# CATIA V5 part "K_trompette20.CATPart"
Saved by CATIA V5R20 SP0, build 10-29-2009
Part number: trompette20
Publications: "Droite.1", "Point.1", "Plan.3"
Bounding box of the stored display mesh (mm): x -49.997 to 49.997, y -49.994 to 49.994, z 0 to 320
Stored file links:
  G:\Khaled_CFAO_2011\SIL\SIL_GR1\gperrin\Khaled\CAD_CATIA\Khaled\K_trompette20.CATPart
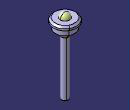
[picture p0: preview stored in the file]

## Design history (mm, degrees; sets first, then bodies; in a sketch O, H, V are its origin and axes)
Set1
  Plane1: stored without definition
  Plane2: stored without definition
  Point1: (0, 300, 0)
  Point2: (0, 0, 300)
  Point3: (0, 20, 300)
  Point4: type Center, Curve edge [face of Shaft1 from Sketch1.L8 | face of Shaft1 from Sketch1.L7]
Body1 (main body)
  Sketch1 on yz-plane, origin (0, 0, 0), H (0, 1, 0), V (0, 0, 1)
    axis line L1 (0, 86) -> (0, -93)
    point P1 (0, 86)
    line L2 (15, 234) -> (15, 0)
    line L3 (41, 260) -> (15, 234)
    line L4 (41, 285) -> (41, 260)
    line L5 (50, 285) -> (41, 285)
    line L6 (50, 292.3865) -> (50, 285)
    line L7 (42.3865, 300) -> (50, 292.3865)
    line L8 (0, 300) -> (42.3865, 300)
    line L9 (15, 0) -> (0, 0)
    line L10 (0, 0) -> (0, 300)
    angle L3 L4 = 135
    distance L5 L8 = 15
    length L5 = 9
    distance L2 L1 = 15
    distance L1 L6 = 50
    distance L8 L9 = 300
    coincidence: P1 V
    vertical: L1 V, L10 V
    horizontal: L9 H
  Shaft1: profile Sketch1, axis Sketch1.L1, angle 360
  Split1: SplitPlane Sphere1
Body2 "Corps Spherique a retirer"
  Sphere1: Center Point4, Radius 20, Angle1 -45, Angle3 0, Angle4 180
